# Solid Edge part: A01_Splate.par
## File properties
Author: mokuno
Template: metric.par
Last saved by: edge
Revision: 46
Application: Solid Edge
Material: アルミニウム, 6061-T6
面のスタイル: Aluminum
塗りつぶしのスタイル: ANSI38(Aluminum)
バーチャルスタイル: アルミニウム ポリッシュ
Coef. of Thermal Exp: 0.0
Thermal Conductivity: 180.0
Specific Heat: 920.0
Modulus of Elasticity: 68947570000.0
Poisson's Ratio: 0.33
Yield Stress: 275790280.0
Ultimate Stress: 310264065.0
Elongation: 0.0
File Size: 0
Number of Sheets: 0
Number of Objects: 0
非切断部品: False
文書内容のタイプ: 0
Density: 0.0979772159 lbm/in^3
Accuracy: 0.00
Document Number: SP-2070
Revision: 1
Project Name: Trolley Wheel Assembly
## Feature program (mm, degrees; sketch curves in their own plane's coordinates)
sketch for "ExtrudedProtrusion_1" plane through (0, 0, 0) normal (0, -1, 0) x-axis (1, 0, 0)
  line (-60, 25) -> (60, 25)
  line (60, 25) -> (60, -25)
  line (60, -25) -> (25, -155)
  line (25, -155) -> (-25, -155)
  line (-60, -25) -> (-25, -155)
  line (-60, 25) -> (-60, -25)
  dimension (linear) = 60
  dimension (linear) = 60
  dimension (linear) = 25
extrude "ExtrudedProtrusion_1" add finite 15 along -normal
sketch for "unnamed Hole 1" plane through (18.6044, 0, -42.646) normal (0, -1, 0) x-axis (1, 0, 0)
  hole centre (-18.6044, -77.354) bore radius 15
hole "unnamed Hole 1" through
sketch for "unnamed Hole 2" plane through (18.6044, 0, -42.646) normal (0, -1, 0) x-axis (1, 0, 0)
  hole centre (11.3956, 42.646) bore radius 10
hole "unnamed Hole 2" through
sketch for "unnamed Hole 3" plane through (18.6044, 0, -42.646) normal (0, -1, 0) x-axis (1, 0, 0)
  hole centre (-48.6044, 42.646) bore radius 10
hole "unnamed Hole 3" through
holes "UserDefinedPattern_1": "unnamed Hole 2", "unnamed Hole 3"
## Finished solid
Body 1: solid body, 11 faces, 24 edges, 12 vertices.
  Faces by surface: plane 8, cylinder 3
  Edges by curve: line 18, circle 6
Bounding box of the edges (mm): 120.000 x 15.000 x 180.000, from (-60, 0, -155) to (60, 15, 25).
Cylindrical faces by radius (mm): R10 x2, R15 x1
Planar faces by outward normal: +x 1, +y 1, +z 1, -x 1, -y 1, -z 1, oblique 2
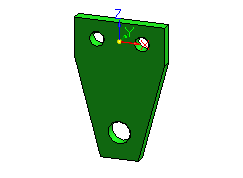
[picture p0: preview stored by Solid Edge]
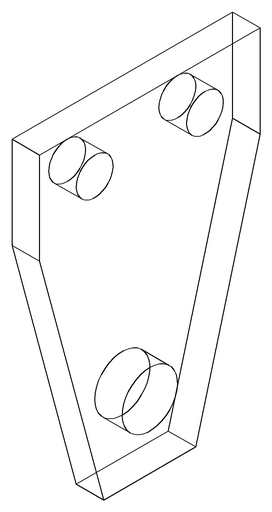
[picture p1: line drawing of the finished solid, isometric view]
